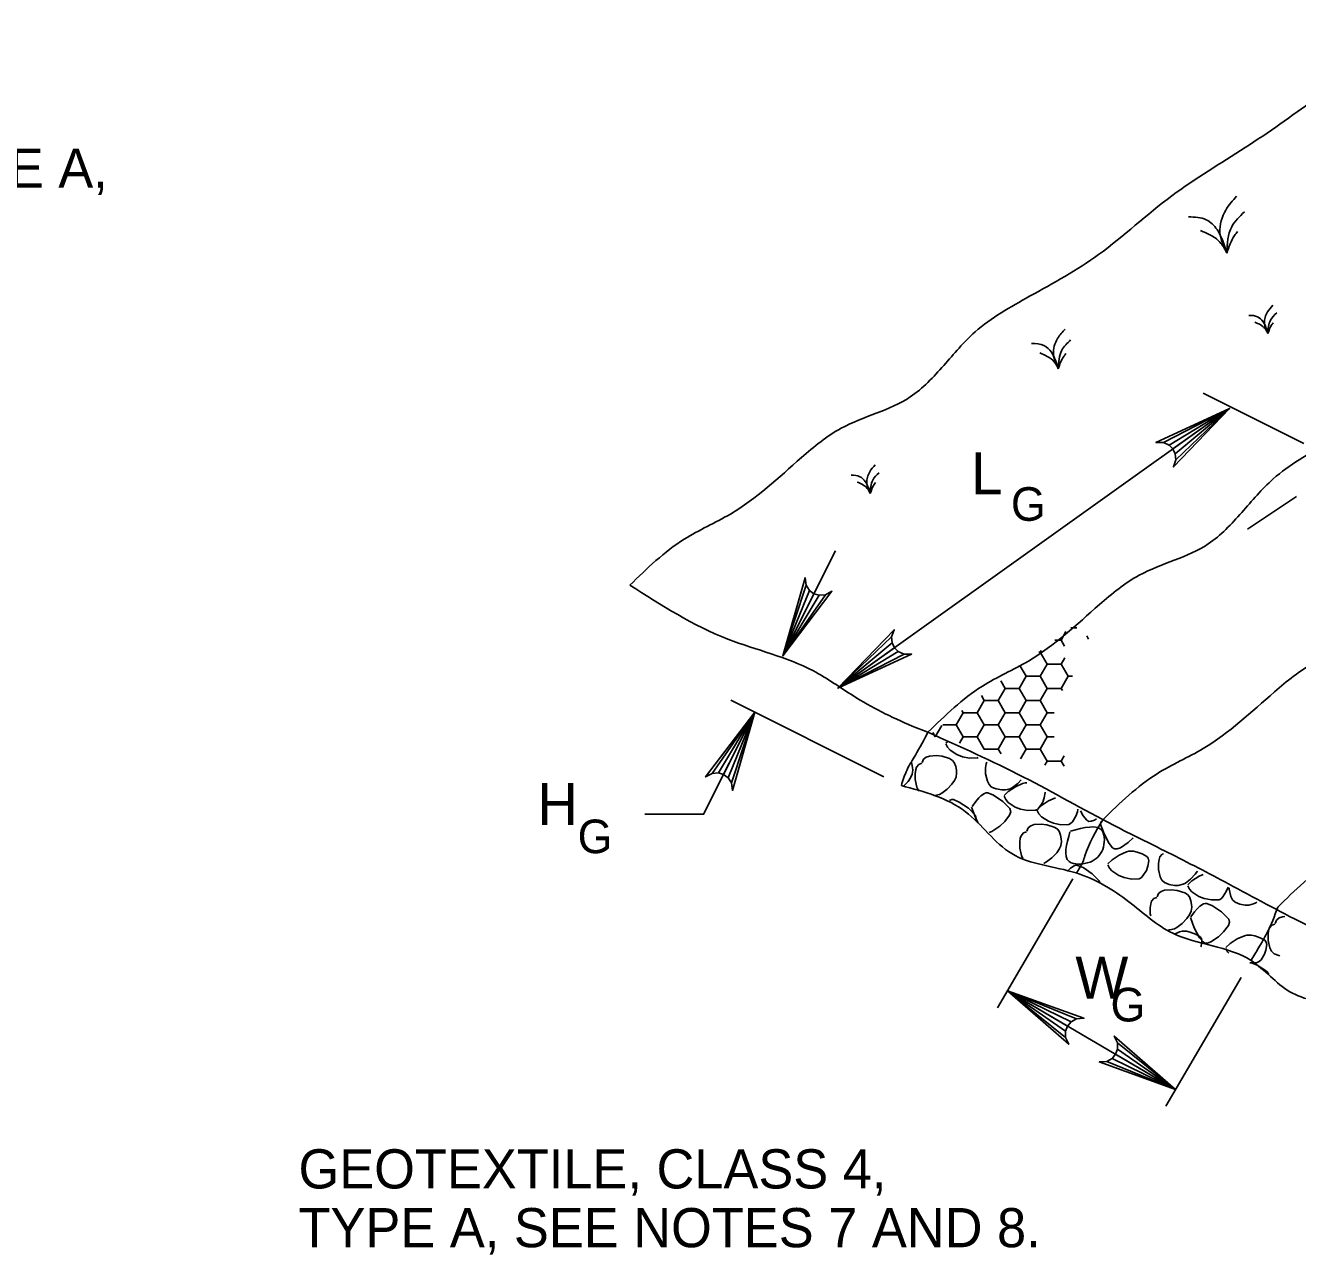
# Model space of a CAD drawing. Extents: x 3 to 3592, y -602 to 1171.
# Drawn here: x 298.8 to 412.5, y 810.9 to 920.7 of the extents above; entities that cross this region are included whole.
import ezdxf

# ---------------------------------------------------------------- set-up
doc = ezdxf.new("R2010")
doc.units = 0
doc.layers.add('2', color=7, linetype='Continuous')
doc.layers.add('3', color=7, linetype='Continuous')

msp = doc.modelspace()

# ---------------------------------------------------------------- linework, layer by layer
at = {"layer": '2'}
for p, q in [((413.05, 883.31), (404.04, 887.82)), ((406.41, 886.46), (393.81, 877.46)), ((412.39, 878.59), (408.01, 875.68)), ((393.81, 877.46), (371.41, 861.46)), ((366.49, 864.35), (371.19, 873.74)), ((375.51, 853.55), (361.84, 860.39)), ((378.05, 858.07), (379.46, 857.53)), ((392.41, 844.43), (385.68, 832.92)), ((407.44, 835.63), (400.71, 824.12)), ((401.59, 825.63), (386.56, 834.43))]:
    msp.add_line(p, q, dxfattribs=at)
for points in [[(406.41, 886.46), (401.39, 881.23), (401.61, 881.86), (406.41, 886.46), (401.56, 882.41), (401.35, 882.85), (406.41, 886.46), (401.01, 883.19), (400.5, 883.41), (406.41, 886.46), (399.83, 883.4), (400.5, 883.41), (401.01, 883.19), (401.35, 882.85), (401.56, 882.41), (401.61, 881.86)], [(366.49, 864.35), (368.48, 871.33), (368.58, 870.66), (366.49, 864.35), (368.88, 870.2), (369.27, 869.91), (366.49, 864.35), (369.74, 869.77), (370.29, 869.81), (366.49, 864.35), (370.88, 870.13), (370.29, 869.81), (369.74, 869.77), (369.27, 869.91), (368.88, 870.2), (368.58, 870.66)], [(371.41, 861.46), (376.44, 866.69), (376.21, 866.06), (371.41, 861.46), (376.26, 865.51), (376.47, 865.07), (371.41, 861.46), (376.81, 864.73), (377.32, 864.51), (371.41, 861.46), (377.99, 864.51), (377.32, 864.51), (376.81, 864.73), (376.47, 865.07), (376.26, 865.51), (376.21, 866.06)], [(391.36, 865.77), (391.79, 866.52)], [(392.23, 866.86), (392.76, 866.86)], [(392.76, 866.86), (392.23, 866.86)], [(390.8, 865.77), (391.36, 865.77)], [(391.36, 865.77), (391.67, 865.23)], [(391.67, 865.23), (391.36, 865.77)], [(393.64, 866.15), (393.81, 865.86)], [(389.37, 864.69), (389.49, 864.69)], [(389.49, 864.69), (389.37, 864.69)], [(389.57, 864.84), (389.49, 864.69)], [(389.49, 864.69), (389.57, 864.84)], [(389.49, 864.69), (390.11, 863.61)], [(390.11, 863.61), (389.49, 864.69)], [(391.69, 864.18), (391.36, 863.61)], [(391.36, 863.61), (391.69, 864.18)], [(387.71, 863.43), (388.24, 862.53)], [(388.24, 862.53), (387.71, 863.43)], [(390.11, 863.61), (389.49, 862.53)], [(391.36, 863.61), (390.11, 863.61)], [(392.37, 862.53), (391.99, 862.53), (391.36, 863.61)], [(386.36, 861.44), (385.97, 862.12)], [(385.97, 862.12), (386.36, 861.44)], [(388.24, 862.53), (387.61, 861.44)], [(389.49, 862.53), (388.24, 862.53)], [(391.36, 861.44), (391.99, 862.53), (392.37, 862.53)], [(384.49, 860.36), (384.23, 860.8)], [(384.23, 860.8), (384.49, 860.36)], [(386.36, 861.44), (385.74, 860.36)], [(387.61, 861.44), (386.36, 861.44)], [(389.49, 860.36), (390.11, 861.44), (391.36, 861.44), (391.47, 861.25)], [(391.47, 861.25), (391.36, 861.44)], [(382.61, 859.28), (382.49, 859.48)], [(382.49, 859.48), (382.61, 859.28)], [(384.49, 860.36), (383.86, 859.28)], [(385.74, 860.36), (384.49, 860.36)], [(390.75, 859.28), (390.11, 859.28), (389.49, 860.36)], [(363.98, 859.32), (359.41, 850.2), (354.16, 850.2)], [(363.98, 859.32), (361.98, 852.34), (361.89, 853.01), (363.98, 859.32), (361.59, 853.47), (361.2, 853.76), (363.98, 859.32), (360.73, 853.9), (360.18, 853.86), (363.98, 859.32), (359.59, 853.54), (360.18, 853.86), (360.73, 853.9), (361.2, 853.76), (361.59, 853.47), (361.89, 853.01)], [(382.61, 859.28), (381.99, 858.2)], [(381.99, 858.2), (382.61, 859.28)], [(383.86, 859.28), (382.61, 859.28)], [(382.61, 859.28), (383.86, 859.28)], [(383.86, 859.28), (384.49, 858.2)], [(389.49, 858.2), (390.11, 859.28), (390.75, 859.28)], [(379.88, 857.51), (380.11, 857.11)], [(380.11, 857.11), (380.69, 858.12)], [(380.11, 857.11), (380.11, 857.11)], [(380.11, 857.11), (380.11, 857.11)], [(381.99, 858.2), (380.79, 858.2)], [(380.79, 858.2), (381.99, 858.2)], [(382.61, 857.11), (381.99, 858.2)], [(381.99, 858.2), (382.61, 857.11)], [(382.61, 857.11), (382.29, 856.55)], [(383.86, 857.11), (382.61, 857.11)], [(384.49, 858.2), (383.86, 857.11)], [(383.86, 857.11), (384.49, 858.2)], [(384.49, 856.03), (383.86, 857.11)], [(384.49, 858.2), (385.74, 858.2)], [(385.74, 858.2), (386.36, 857.11)], [(386.36, 857.11), (385.74, 856.03)], [(390.75, 857.11), (390.11, 857.11), (389.49, 858.2)], [(381.07, 856.57), (381.2, 856.69)], [(381.21, 856.19), (381.07, 856.49)], [(381.44, 855.94), (381.21, 856.19)], [(384.46, 855.99), (384.49, 856.03)], [(384.49, 856.03), (385.74, 856.03)], [(385.74, 856.03), (384.49, 856.03)], [(385.74, 856.03), (385.99, 855.6)], [(387.73, 855.15), (388.24, 856.03)], [(388.24, 856.03), (389.49, 856.03)], [(389.49, 856.03), (390.11, 854.95)], [(378.94, 854.82), (379.05, 855.13)], [(379.05, 855.13), (379.3, 855.31)], [(379.3, 855.31), (379.59, 855.41)], [(379.59, 855.41), (380.22, 855.46)], [(380.22, 855.46), (380.72, 855.4)], [(380.72, 855.4), (381.39, 855.18)], [(381.39, 855.18), (381.65, 855.02)], [(382.05, 855.53), (381.44, 855.94)], [(381.65, 855.02), (381.81, 854.82)], [(382.53, 855.35), (382.05, 855.53)], [(383.17, 855.21), (382.53, 855.35)], [(383.87, 855.24), (383.17, 855.21)], [(383.94, 855.27), (383.87, 855.24)], [(384.66, 854.7), (384.72, 854.87)], [(390.11, 854.95), (389.9, 854.59)], [(389.9, 854.59), (390.11, 854.95)], [(390.11, 854.95), (391.36, 854.95)], [(391.36, 854.95), (391.63, 855.42)], [(391.36, 854.95), (391.62, 854.5)], [(391.62, 854.5), (391.36, 854.95)], [(378.05, 853.78), (377.91, 853.46)], [(377.98, 854.84), (378.03, 854.71)], [(378.03, 854.71), (378.09, 854.39)], [(378.1, 854.14), (378.05, 853.78)], [(378.09, 854.39), (378.1, 854.14)], [(378.3, 853.83), (378.36, 854.19)], [(378.31, 853.3), (378.3, 853.83)], [(378.36, 854.19), (378.44, 854.42)], [(378.44, 854.42), (378.63, 854.66)], [(378.63, 854.66), (378.9, 854.76)], [(381.81, 854.82), (381.95, 854.46)], [(381.95, 854.46), (382.01, 854.14)], [(382.02, 853.89), (381.97, 853.52)], [(382.01, 854.14), (382.02, 853.89)], [(384.6, 854.34), (384.66, 854.7)], [(384.61, 853.82), (384.6, 854.34)], [(384.77, 853.16), (384.61, 853.82)], [(377.68, 853.14), (377.28, 852.71)], [(377.91, 853.46), (377.68, 853.14)], [(378.46, 852.64), (378.31, 853.3)], [(378.62, 852.34), (378.46, 852.64)], [(381.6, 852.88), (381.18, 852.44)], [(381.83, 853.21), (381.6, 852.88)], [(381.97, 853.52), (381.83, 853.21)], [(384.92, 852.86), (384.77, 853.16)], [(385.15, 852.63), (384.92, 852.86)], [(385.56, 852.47), (385.15, 852.63)], [(386.64, 852.25), (387.27, 852.67)], [(387.01, 852.59), (386.8, 852.49)], [(387.48, 852.96), (387.01, 852.59)], [(387.27, 852.67), (387.92, 852.96)], [(387.78, 853.28), (387.48, 852.96)], [(387.92, 852.96), (388.13, 853.01)], [(388.13, 853.01), (388.3, 853.01)], [(378.68, 852.28), (378.62, 852.34)], [(380.08, 851.88), (379.98, 851.87)], [(380.49, 851.97), (380.08, 851.88)], [(380.7, 852.08), (380.49, 851.97)], [(381.18, 852.44), (380.7, 852.08)], [(381.39, 851.44), (381.43, 851.47)], [(381.43, 851.47), (381.59, 851.51)], [(381.59, 851.51), (381.74, 851.51)], [(381.74, 851.51), (382.25, 851.3)], [(383.73, 851.34), (383.99, 851.66)], [(383.99, 851.66), (384.19, 851.86)], [(384.19, 851.86), (384.51, 852.07)], [(384.51, 852.07), (384.66, 852.11)], [(384.66, 852.11), (384.81, 852.11)], [(384.81, 852.11), (385.32, 851.9)], [(385.32, 851.9), (386.14, 851.34)], [(386.05, 852.39), (385.56, 852.47)], [(386.38, 852.39), (386.05, 852.39)], [(386.26, 851.89), (386.64, 852.25)], [(386.41, 851.51), (386.26, 851.81)], [(386.8, 852.49), (386.38, 852.39)], [(386.63, 851.26), (386.41, 851.51)], [(389.85, 851.67), (389.71, 851.3)], [(389.92, 852.15), (389.85, 851.67)], [(389.92, 852.17), (389.92, 852.15)], [(390.23, 851.4), (390.86, 851.68)], [(382.25, 851.3), (383.07, 850.74)], [(383.07, 850.74), (383.7, 850.11)], [(383.7, 849.91), (383.36, 850.83)], [(383.4, 850.89), (383.73, 851.34)], [(386.14, 851.34), (386.77, 850.71)], [(387.25, 850.85), (386.63, 851.26)], [(386.85, 850.43), (386.75, 850.13)], [(386.77, 850.71), (386.85, 850.43)], [(387.73, 850.67), (387.25, 850.85)], [(388.37, 850.53), (387.73, 850.67)], [(389.07, 850.56), (388.37, 850.53)], [(389.24, 850.64), (389.07, 850.56)], [(389.23, 850.62), (389.61, 850.98)], [(389.38, 850.24), (389.23, 850.54)], [(389.4, 850.81), (389.24, 850.64)], [(389.71, 851.3), (389.4, 850.81)], [(389.61, 850.98), (390.23, 851.4)], [(392.82, 850.41), (392.67, 850.03)], [(392.85, 850.65), (392.82, 850.41)], [(393.34, 850.06), (393.1, 850.52)], [(383.7, 850.11), (383.77, 849.83)], [(383.95, 849.44), (383.7, 849.91)], [(383.77, 849.83), (383.71, 849.65)], [(386.32, 849.55), (385.87, 849.13)], [(386.75, 850.13), (386.32, 849.55)], [(388.41, 849), (388.66, 849.18)], [(388.66, 849.18), (388.95, 849.28)], [(388.95, 849.28), (389.58, 849.33)], [(389.6, 849.99), (389.38, 850.24)], [(389.58, 849.33), (390.08, 849.27)], [(390.22, 849.58), (389.6, 849.99)], [(390.08, 849.27), (390.75, 849.05)], [(390.69, 849.4), (390.22, 849.58)], [(391.34, 849.27), (390.69, 849.4)], [(392.04, 849.29), (391.34, 849.27)], [(392.2, 849.37), (392.04, 849.29)], [(392.37, 849.54), (392.2, 849.37)], [(392.67, 850.03), (392.37, 849.54)], [(393.66, 849.68), (393.34, 850.06)], [(393.83, 849.57), (393.66, 849.68)], [(394.05, 849.58), (393.83, 849.57)], [(394.35, 849.69), (394.05, 849.58)], [(394.51, 849.79), (394.35, 849.69)], [(395.19, 848.46), (394.84, 849.39)], [(394.88, 849.45), (394.96, 849.55)], [(385.17, 848.67), (384.93, 848.58)], [(385.87, 849.13), (385.17, 848.67)], [(387.66, 847.7), (387.71, 848.06)], [(387.71, 848.06), (387.8, 848.29)], [(387.8, 848.29), (387.99, 848.54)], [(387.99, 848.54), (388.26, 848.64)], [(388.3, 848.7), (388.41, 849)], [(390.75, 849.05), (391.01, 848.89)], [(391.01, 848.89), (391.17, 848.7)], [(391.17, 848.7), (391.31, 848.33)], [(391.31, 848.33), (391.37, 848.01)], [(395.64, 847.6), (395.19, 848.46)], [(397.79, 848.09), (397.36, 847.69)], [(387.67, 847.18), (387.66, 847.7)], [(387.82, 846.52), (387.67, 847.18)], [(391.19, 847.08), (390.96, 846.76)], [(391.33, 847.4), (391.19, 847.08)], [(391.38, 847.76), (391.33, 847.4)], [(391.37, 848.01), (391.38, 847.76)], [(395.96, 847.21), (395.64, 847.6)], [(396.14, 847.11), (395.96, 847.21)], [(396.36, 847.11), (396.14, 847.11)], [(396.65, 847.22), (396.36, 847.11)], [(397.36, 847.69), (396.65, 847.22)], [(397.19, 846.85), (397.4, 846.9)], [(397.4, 846.9), (397.82, 846.9)], [(397.82, 846.9), (398.14, 846.83)], [(387.95, 846.26), (387.82, 846.52)], [(389.85, 845.84), (389.82, 845.84)], [(390.06, 845.95), (389.85, 845.84)], [(390.54, 846.32), (390.06, 845.95)], [(390.96, 846.76), (390.54, 846.32)], [(395.53, 845.78), (395.91, 846.14)], [(395.91, 846.14), (396.54, 846.55)], [(396.54, 846.55), (397.19, 846.85)], [(398.14, 846.83), (398.61, 846.66)], [(398.61, 846.66), (399.01, 846.44)], [(399.01, 846.44), (399.15, 846.27)], [(399.19, 846.04), (399.12, 845.56)], [(399.15, 846.27), (399.19, 846.04)], [(400.05, 845.81), (400.11, 846.16)], [(400.06, 845.28), (400.05, 845.81)], [(400.11, 846.16), (400.19, 846.39)], [(400.19, 846.39), (400.38, 846.64)], [(400.38, 846.64), (400.5, 846.68)], [(392.01, 845.21), (392.2, 845.4)], [(392.2, 845.4), (392.51, 845.6)], [(392.51, 845.6), (392.66, 845.65)], [(392.66, 845.65), (392.81, 845.64)], [(392.81, 845.64), (393.33, 845.44)], [(393.33, 845.44), (394.14, 844.88)], [(394.14, 844.88), (394.77, 844.25)], [(395.68, 845.4), (395.53, 845.7)], [(395.9, 845.14), (395.68, 845.4)], [(396.52, 844.74), (395.9, 845.14)], [(397, 844.56), (396.52, 844.74)], [(398.67, 844.7), (398.51, 844.53)], [(398.98, 845.18), (398.67, 844.7)], [(399.12, 845.56), (398.98, 845.18)], [(400.22, 844.62), (400.06, 845.28)], [(400.37, 844.32), (400.22, 844.62)], [(403.35, 844.86), (402.93, 844.42)], [(403.05, 844.26), (403.68, 844.68)], [(403.53, 845.11), (403.35, 844.86)], [(403.68, 844.68), (404.04, 844.84)], [(394.77, 844.25), (394.83, 844.04)], [(397.64, 844.42), (397, 844.56)], [(398.34, 844.44), (397.64, 844.42)], [(398.51, 844.53), (398.34, 844.44)], [(400.6, 844.1), (400.37, 844.32)], [(401.01, 843.93), (400.6, 844.1)], [(400.6, 843.42), (401.23, 843.47)], [(401.5, 843.85), (401.01, 843.93)], [(401.23, 843.47), (401.73, 843.41)], [(401.83, 843.85), (401.5, 843.85)], [(402.25, 843.95), (401.83, 843.85)], [(402.46, 844.05), (402.25, 843.95)], [(402.93, 844.42), (402.46, 844.05)], [(402.68, 843.9), (403.05, 844.26)], [(402.82, 843.53), (402.68, 843.82)], [(403.05, 843.27), (402.82, 843.53)], [(406.27, 843.69), (406.12, 843.31)], [(406.27, 843.69), (406.27, 843.69)], [(406.37, 843.53), (406.37, 843.64)], [(406.53, 842.87), (406.37, 843.53)], [(399.36, 842.2), (399.44, 842.43)], [(399.44, 842.43), (399.64, 842.68)], [(399.64, 842.68), (399.91, 842.78)], [(399.95, 842.84), (400.06, 843.14)], [(400.06, 843.14), (400.3, 843.32)], [(400.3, 843.32), (400.6, 843.42)], [(401.73, 843.41), (402.4, 843.19)], [(402.4, 843.19), (402.65, 843.03)], [(402.65, 843.03), (402.82, 842.84)], [(402.82, 842.84), (402.96, 842.47)], [(402.96, 842.47), (403.02, 842.15)], [(403.66, 842.87), (403.05, 843.27)], [(404.14, 842.68), (403.66, 842.87)], [(404.78, 842.55), (404.14, 842.68)], [(405.49, 842.57), (404.78, 842.55)], [(405.65, 842.66), (405.49, 842.57)], [(405.82, 842.82), (405.65, 842.66)], [(406.12, 843.31), (405.82, 842.82)], [(406.68, 842.57), (406.53, 842.87)], [(406.91, 842.34), (406.68, 842.57)], [(407.32, 842.18), (406.91, 842.34)], [(408.84, 842.36), (408.77, 842.3)], [(399.3, 841.84), (399.36, 842.2)], [(399.32, 841.32), (399.3, 841.84)], [(399.36, 841.12), (399.32, 841.32)], [(402.84, 841.22), (402.6, 840.9)], [(402.98, 841.54), (402.84, 841.22)], [(402.96, 841.03), (403.29, 841.48)], [(403.03, 841.9), (402.98, 841.54)], [(403.02, 842.15), (403.03, 841.9)], [(403.29, 841.48), (403.55, 841.8)], [(403.55, 841.8), (403.76, 842)], [(403.76, 842), (404.07, 842.21)], [(404.07, 842.21), (404.22, 842.25)], [(404.22, 842.25), (404.37, 842.24)], [(404.37, 842.24), (404.88, 842.04)], [(404.88, 842.04), (405.7, 841.48)], [(405.7, 841.48), (406.33, 840.85)], [(407.81, 842.1), (407.32, 842.18)], [(408.14, 842.1), (407.81, 842.1)], [(408.56, 842.2), (408.14, 842.1)], [(408.77, 842.3), (408.56, 842.2)], [(401.71, 840.09), (401.5, 839.98)], [(402.18, 840.46), (401.71, 840.09)], [(402.6, 840.9), (402.18, 840.46)], [(403.26, 840.05), (402.92, 840.97)], [(406.31, 840.26), (405.88, 839.69)], [(406.41, 840.57), (406.31, 840.26)], [(406.33, 840.85), (406.41, 840.57)], [(409.99, 840.05), (410.18, 840.3)], [(410.18, 840.3), (410.45, 840.4)], [(410.49, 840.46), (410.6, 840.76)], [(410.6, 840.76), (410.84, 840.95)], [(410.84, 840.95), (411.14, 841.05)], [(411.14, 841.05), (411.34, 841.06)], [(401.08, 839.89), (400.96, 839.89)], [(401.5, 839.98), (401.08, 839.89)], [(401.48, 839.49), (401.94, 839.7)], [(401.94, 839.7), (402.16, 839.76)], [(402.16, 839.76), (402.57, 839.75)], [(402.57, 839.75), (402.9, 839.68)], [(402.9, 839.68), (403.37, 839.51)], [(403.72, 839.18), (403.26, 840.05)], [(403.37, 839.51), (403.76, 839.3)], [(404.04, 838.8), (403.72, 839.18)], [(403.76, 839.3), (403.9, 839.12)], [(403.9, 839.12), (403.94, 838.9)], [(405.43, 839.27), (404.73, 838.81)], [(405.88, 839.69), (405.43, 839.27)], [(406.45, 838.65), (407.08, 839.07)], [(407.08, 839.07), (407.73, 839.36)], [(407.73, 839.36), (407.94, 839.42)], [(407.94, 839.42), (408.36, 839.41)], [(408.36, 839.41), (408.68, 839.34)], [(408.68, 839.34), (409.15, 839.17)], [(409.15, 839.17), (409.55, 838.96)], [(409.55, 838.96), (409.69, 838.78)], [(409.85, 839.46), (409.9, 839.82)], [(409.86, 838.94), (409.85, 839.46)], [(410.01, 838.28), (409.86, 838.94)], [(409.9, 839.82), (409.99, 840.05)], [(403.87, 838.42), (403.85, 838.35)], [(403.94, 838.9), (403.87, 838.42)], [(404.21, 838.69), (404.04, 838.8)], [(404.43, 838.7), (404.21, 838.69)], [(404.73, 838.81), (404.43, 838.7)], [(406.07, 838.29), (406.45, 838.65)], [(406.22, 837.92), (406.07, 838.21)], [(406.33, 837.8), (406.22, 837.92)], [(409.66, 838.08), (409.52, 837.7)], [(409.73, 838.56), (409.66, 838.08)], [(409.69, 838.78), (409.73, 838.56)], [(410.16, 837.98), (410.01, 838.28)], [(410.39, 837.75), (410.16, 837.98)], [(408.22, 836.95), (408.22, 836.95)], [(408.22, 836.95), (408.37, 836.95)], [(408.88, 836.96), (408.23, 836.94)], [(408.37, 836.95), (408.89, 836.74)], [(409.05, 837.05), (408.88, 836.96)], [(408.89, 836.74), (409.7, 836.18)], [(409.22, 837.21), (409.05, 837.05)], [(409.52, 837.7), (409.22, 837.21)], [(410.8, 837.59), (410.39, 837.75)], [(410.91, 837.57), (410.8, 837.59)], [(409.7, 836.18), (409.92, 835.96)], [(386.56, 834.43), (393.39, 831.98), (392.72, 831.93), (386.56, 834.43), (392.24, 831.66), (391.92, 831.29), (386.56, 834.43), (391.75, 830.84), (391.76, 830.28), (386.56, 834.43), (392.04, 829.67), (391.76, 830.28), (391.75, 830.84), (391.92, 831.29), (392.24, 831.66), (392.72, 831.93)], [(401.59, 825.63), (394.76, 828.08), (395.43, 828.13), (401.59, 825.63), (395.91, 828.4), (396.23, 828.77), (401.59, 825.63), (396.4, 829.23), (396.39, 829.78), (401.59, 825.63), (396.11, 830.39), (396.39, 829.78), (396.4, 829.23), (396.23, 828.77), (395.91, 828.4), (395.43, 828.13)]]:
    msp.add_lwpolyline(points, dxfattribs=at)
for points in [[(389.49, 862.53), (390.11, 863.61), (391.36, 863.61), (391.99, 862.53), (391.36, 861.44), (390.11, 861.44)], [(387.61, 861.44), (388.24, 862.53), (389.49, 862.53), (390.11, 861.44), (389.49, 860.36), (388.24, 860.36)], [(385.74, 860.36), (386.36, 861.44), (387.61, 861.44), (388.24, 860.36), (387.61, 859.28), (386.36, 859.28)], [(383.86, 859.28), (384.49, 860.36), (385.74, 860.36), (386.36, 859.28), (385.74, 858.2), (384.49, 858.2)], [(387.61, 859.28), (388.24, 860.36), (389.49, 860.36), (390.11, 859.28), (389.49, 858.2), (388.24, 858.2)], [(385.74, 858.2), (386.36, 859.28), (387.61, 859.28), (388.24, 858.2), (387.61, 857.11), (386.36, 857.11)], [(387.61, 857.11), (388.24, 858.2), (389.49, 858.2), (390.11, 857.11), (389.49, 856.03), (388.24, 856.03)]]:
    msp.add_lwpolyline(points, close=True, dxfattribs=at)
for points in [[(352.82, 870.67), (357.68, 874.78), (361.8, 877.02), (368.16, 882.07), (371.71, 884.69), (377.88, 887.49), (380.87, 890.3), (383.67, 893.29), (388.54, 896.47), (394.71, 900.21), (401.25, 905.45), (407.8, 909.75), (413.97, 914.05), (422.82, 920.67)], [(379.46, 857.53), (384.32, 861.65), (388.43, 863.89), (394.79, 868.94), (398.34, 871.56), (404.51, 874.36), (407.5, 877.17), (410.31, 880.16), (415.17, 883.34), (421.34, 887.08), (427.89, 892.31), (434.43, 896.61), (440.6, 900.91), (449.46, 907.53)], [(406.16, 900.33), (405.55, 902.17), (406.07, 904.18), (407.04, 905.41)], [(406.16, 900.33), (406.6, 902.69), (407.74, 904.01)], [(406.16, 900.33), (405.29, 902.43), (404.32, 903.31), (402.75, 903.57)], [(406.16, 900.33), (405.64, 901.2), (404.76, 901.91), (403.8, 902.34)], [(406.16, 900.33), (406.86, 901.91), (407.13, 902.26)], [(395.08, 849.72), (399.94, 853.83), (404.06, 856.08), (410.41, 861.13), (413.97, 863.74), (420.14, 866.55), (423.13, 869.35), (425.93, 872.34), (430.8, 875.52), (436.97, 879.26), (443.51, 884.5), (450.05, 888.8), (456.23, 893.1), (465.08, 899.72)], [(409.84, 893.15), (409.4, 894.2), (408.92, 894.64), (408.13, 894.77)], [(409.84, 893.15), (409.53, 894.07), (409.8, 895.08), (410.28, 895.69)], [(409.84, 893.15), (410.06, 894.33), (410.63, 894.99)], [(391.1, 890), (390.67, 891.29), (391.04, 892.7), (391.72, 893.55)], [(409.84, 893.15), (409.58, 893.59), (409.14, 893.94), (408.66, 894.16)], [(409.84, 893.15), (410.19, 893.94), (410.32, 894.11)], [(391.1, 890), (391.41, 891.65), (392.21, 892.57)], [(391.1, 890), (390.49, 891.47), (389.82, 892.08), (388.71, 892.27)], [(391.1, 890), (390.74, 890.61), (390.12, 891.1), (389.45, 891.41)], [(391.1, 890), (391.59, 891.1), (391.78, 891.35)], [(410.71, 841.91), (415.57, 846.02), (419.68, 848.26), (426.04, 853.31), (429.59, 855.93), (435.76, 858.74), (438.75, 861.54), (441.56, 864.53), (446.42, 867.71), (452.59, 871.45), (459.14, 876.69), (465.68, 880.99), (471.85, 885.29), (480.71, 891.91)], [(374.3, 878.87), (373.99, 879.79), (374.26, 880.8), (374.74, 881.41)], [(374.3, 878.87), (373.86, 879.93), (373.38, 880.36), (372.59, 880.49)], [(374.3, 878.87), (374.04, 879.31), (373.6, 879.66), (373.12, 879.88)], [(374.3, 878.87), (374.52, 880.06), (375.09, 880.71)], [(374.3, 878.87), (374.65, 879.66), (374.78, 879.84)], [(352.82, 870.67), (361.58, 865.85), (369.22, 863.01), (372.79, 860.78), (375.31, 859.36), (378.05, 858.07)], [(377.08, 852.77), (377.59, 854.17), (378.33, 855.48), (379.46, 857.53)], [(379.46, 857.53), (387.99, 853.53), (396.03, 849.23), (400.89, 846.8), (406.31, 843.99), (413.05, 840.44), (420.52, 837.08), (427.44, 833.71), (431.56, 830.53), (437.73, 827.91), (441.96, 826.28)], [(441.96, 820.03), (437.42, 823.13), (432, 824.62), (423.95, 829.33), (416.11, 833.04), (411.8, 834.35), (408.33, 837.14), (401.33, 839.58), (397.41, 842.39), (392.7, 844.96), (386.94, 846.69), (382.82, 850.43), (377.08, 852.77)], [(392.19, 848.69), (395.05, 848.69), (395.07, 847.07), (393.94, 845.94), (392.08, 845.98), (392.15, 848.63)], [(392.7, 844.96), (393.29, 845.94), (393.48, 846.5), (395.08, 849.72)], [(408.33, 837.14), (409, 838.27), (409.75, 839.58), (410.71, 841.91)]]:
    msp.add_spline(points, degree=3, dxfattribs=at)

# ---------------------------------------------------------------- texts
at = {"layer": '3'}
for s, height, p in [('GEOTEXTILE, CLASS 4, TYPE A,', 3.5, (234.38, 906.17)), ('L', 3.75, (383.32, 878.79)), ('G', 3, (386.87, 876.42)), ('H', 3.75, (344.56, 849.24)), ('G', 3, (348.15, 846.73)), ('W', 3.75, (392.63, 833.74)), ('G', 3, (395.77, 831.7)), ('GEOTEXTILE, CLASS 4, ', 3.5, (323.21, 816.78)), ('TYPE A, SEE NOTES 7 AND 8.', 3.5, (323.21, 811.53))]:
    msp.add_text(s, height=height, dxfattribs=at).set_placement(p)

doc.saveas('drawing.dxf')
